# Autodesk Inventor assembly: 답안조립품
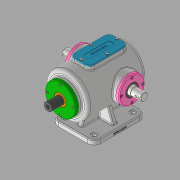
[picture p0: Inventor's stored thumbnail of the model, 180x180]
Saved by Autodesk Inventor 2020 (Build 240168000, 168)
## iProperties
Created: 2021-11
Part Number: 답안조립품
Document SubType Name: Assembly
Designer: Administrator
Author: Administrator
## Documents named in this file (14)
- C:\Users\Administrator\Desktop\711106V1022\답안조립품.iam
- C:\Users\Administrator\Desktop\711106V1022\본체.ipt
- C:\Users\Administrator\Desktop\711106V1022\베어링 6205.ipt
- 베어링 6205.ipt
- C:\Users\Administrator\Desktop\711106V1022\볼트 M4x0.7.ipt
- C:\Users\Administrator\Desktop\711106V1022\부시.ipt
- C:\Users\Administrator\Desktop\711106V1022\상부커버.ipt
- C:\Users\Administrator\Desktop\711106V1022\슬라이드 커버.ipt
- C:\Users\Administrator\Desktop\711106V1022\슬라이드.ipt
- C:\Users\Administrator\Desktop\711106V1022\오일실.ipt
- 오일실.ipt
- C:\Users\Administrator\Desktop\711106V1022\육각머리볼트 M4.ipt
- C:\Users\Administrator\Desktop\711106V1022\축 커버.ipt
- C:\Users\Administrator\Desktop\711106V1022\편심축.ipt
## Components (12 placed, 1 different names)
1. M4x0.7:1 — 각도:4
2. M4x0.7:4
3. M4x0.7:5
4. M4x0.7:6
5. M4x0.7:2 — 각도:5
6. M4x0.7:7
7. M4x0.7:8
8. M4x0.7:9
9. M4x0.7:10 — 각도:6
10. M4x0.7:11
11. M4x0.7:12
12. M4x0.7:13
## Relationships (3: Angle 3)
- 각도:4 [Angle]: M4x0.7:1
- 각도:5 [Angle]: M4x0.7:2
- 각도:6 [Angle]: M4x0.7:10
